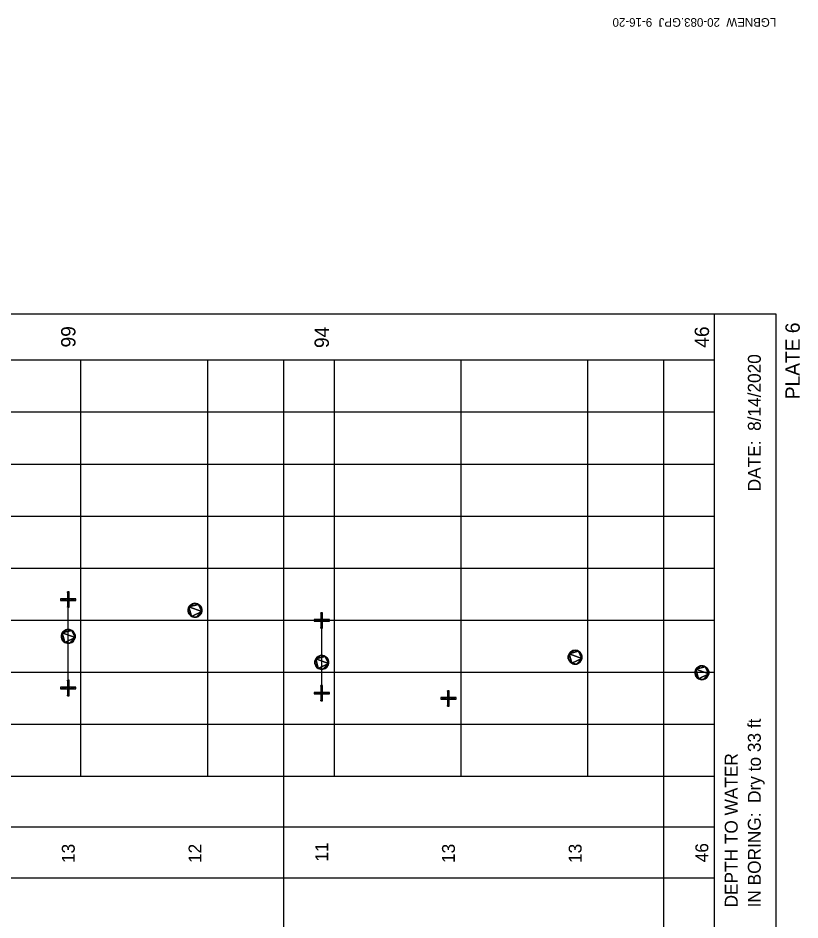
# Model space of a CAD drawing. Extents: x 1313964 to 1316843, y 2087046 to 2096619.
# Drawn here: x 1314106.81 to 1314137.66, y 2089837.67 to 2089873.26 of the extents above; entities that cross this region are included whole.
import ezdxf

# ---------------------------------------------------------------- set-up
doc = ezdxf.new("R2010")
doc.units = 0
doc.layers.add('B-Sub-Contour', color=7, linetype='Continuous')
doc.layers.add('Default', color=7, linetype='Continuous')

# ---------------------------------------------------------------- blocks, each defined once
blk = doc.blocks.new('POINT_DISPLAY')
at = {"layer": 'Default'}
blk.add_line((0, 0), (0, 0), dxfattribs=at)
blk = doc.blocks.new('DMK_101')
at = {"layer": 'Default'}
for points in [[(-14269.212, 2386.584), (-14476.476, 0), (-14269.212, -2386.584), (-14269.212, 2386.584)], [(-12638.532, 6858), (-13653.516, 4690.872), (-14269.212, 2386.584), (-12638.532, 6858)], [(-12638.532, 6858), (-14269.212, 2386.584), (-14269.212, -2386.584), (-12638.532, 6858)], [(-12638.532, 6858), (-14269.212, -2386.584), (-3147.06, -13508.736), (-12638.532, 6858)], [(-3147.06, 13511.784), (-7618.476, 11878.056), (-12638.532, 6858), (-3147.06, 13511.784)], [(6097.524, 11878.056), (-3147.06, 13511.784), (-12638.532, 6858), (6097.524, 11878.056)], [(-7618.476, 11878.056), (-11266.932, 8820.912), (-12638.532, 6858), (-7618.476, 11878.056)], [(-3147.06, -13508.736), (6097.524, 11878.056), (-12638.532, 6858), (-3147.06, -13508.736)], [(-7618.476, 11878.056), (-9578.34, 10506.456), (-11266.932, 8820.912), (-7618.476, 11878.056)], [(-9578.34, 10506.456), (-10456.164, 9698.736), (-11266.932, 8820.912), (-9578.34, 10506.456)], [(-3147.06, 13511.784), (-5451.348, 12893.04), (-7618.476, 11878.056), (-3147.06, 13511.784)], [(1626.108, 13511.784), (-760.476, 13712.952), (-3147.06, 13511.784), (1626.108, 13511.784)], [(6097.524, 11878.056), (1626.108, 13511.784), (-3147.06, 13511.784), (6097.524, 11878.056)], [(-3147.06, -13508.736), (11117.58, -6858), (6097.524, 11878.056), (-3147.06, -13508.736)], [(6097.524, 11878.056), (3930.396, 12893.04), (1626.108, 13511.784), (6097.524, 11878.056)], [(11117.58, 6858), (8060.436, 10506.456), (6097.524, 11878.056), (11117.58, 6858)], [(12751.308, 2386.584), (11117.58, 6858), (6097.524, 11878.056), (12751.308, 2386.584)], [(11117.58, -6858), (12751.308, 2386.584), (6097.524, 11878.056), (11117.58, -6858)], [(9745.98, 8820.912), (8938.26, 9698.736), (8060.436, 10506.456), (9745.98, 8820.912)], [(11117.58, 6858), (9745.98, 8820.912), (8060.436, 10506.456), (11117.58, 6858)], [(12751.308, 2386.584), (12132.564, 4690.872), (11117.58, 6858), (12751.308, 2386.584)], [(11117.58, -6858), (12751.308, -2386.584), (12751.308, 2386.584), (11117.58, -6858)], [(12751.308, -2386.584), (12952.476, 0), (12751.308, 2386.584), (12751.308, -2386.584)], [(-14269.212, -2386.584), (-13653.516, -4690.872), (-12638.532, -6858), (-14269.212, -2386.584)], [(-14269.212, -2386.584), (-12638.532, -6858), (-9578.34, -10506.456), (-14269.212, -2386.584)], [(-14269.212, -2386.584), (-9578.34, -10506.456), (-3147.06, -13508.736), (-14269.212, -2386.584)], [(-12638.532, -6858), (-11266.932, -8817.864), (-9578.34, -10506.456), (-12638.532, -6858)], [(-11266.932, -8817.864), (-10456.164, -9695.688), (-9578.34, -10506.456), (-11266.932, -8817.864)], [(-9578.34, -10506.456), (-7618.476, -11878.056), (-3147.06, -13508.736), (-9578.34, -10506.456)], [(-7618.476, -11878.056), (-5451.348, -12893.04), (-3147.06, -13508.736), (-7618.476, -11878.056)], [(-3147.06, -13508.736), (6097.524, -11878.056), (11117.58, -6858), (-3147.06, -13508.736)], [(-3147.06, -13508.736), (1626.108, -13508.736), (6097.524, -11878.056), (-3147.06, -13508.736)], [(-3147.06, -13508.736), (-760.476, -13716), (1626.108, -13508.736), (-3147.06, -13508.736)], [(1626.108, -13508.736), (3930.396, -12893.04), (6097.524, -11878.056), (1626.108, -13508.736)], [(6097.524, -11878.056), (8060.436, -10506.456), (11117.58, -6858), (6097.524, -11878.056)], [(8060.436, -10506.456), (9745.98, -8817.864), (11117.58, -6858), (8060.436, -10506.456)], [(8060.436, -10506.456), (8938.26, -9695.688), (9745.98, -8817.864), (8060.436, -10506.456)], [(11117.58, -6858), (12132.564, -4690.872), (12751.308, -2386.584), (11117.58, -6858)]]:
    blk.add_lwpolyline(points, close=True, dxfattribs=at)
blk.add_blockref('POINT_DISPLAY', (14479.524, 0), dxfattribs=at)
blk = doc.blocks.new('DMK_99')
at = {"layer": 'Default'}
for points in [[(-1524, -1524), (-1524, 1524), (-15240, 1524), (-1524, -1524)], [(-1524, -1524), (-15240, 1524), (-15240, -1524), (-1524, -1524)], [(1524, 1524), (1524, 15240), (-1524, 15240), (1524, 1524)], [(1524, 1524), (-1524, 15240), (-1524, 1524), (1524, 1524)], [(-1524, -1524), (1524, -1524), (1524, 1524), (-1524, -1524)], [(-1524, -1524), (1524, 1524), (-1524, 1524), (-1524, -1524)], [(1524, -1524), (15240, -1524), (15240, 1524), (1524, -1524)], [(1524, -1524), (15240, 1524), (1524, 1524), (1524, -1524)], [(-1524, -1524), (-1524, -15240), (1524, -15240), (-1524, -1524)], [(-1524, -1524), (1524, -15240), (1524, -1524), (-1524, -1524)]]:
    blk.add_lwpolyline(points, close=True, dxfattribs=at)

msp = doc.modelspace()

# ---------------------------------------------------------------- linework, layer by layer
at = {"layer": 'B-Sub-Contour'}
for points in [[(1314136.725, 2089818.705), (1314136.725, 2089861.576), (1314075.306, 2089861.576), (1314075.306, 2089818.705), (1314136.725, 2089818.705)], [(1314134.292, 2089818.705), (1314134.292, 2089861.576)], [(1314134.292, 2089859.752), (1314082.603, 2089859.752)], [(1314134.292, 2089859.752), (1314089.292, 2089859.752)], [(1314109.292, 2089843.333), (1314109.292, 2089859.752)], [(1314114.292, 2089843.333), (1314114.292, 2089859.752)], [(1314117.292, 2089839.319), (1314117.292, 2089859.752)], [(1314119.292, 2089843.333), (1314119.292, 2089859.752)], [(1314124.292, 2089843.333), (1314124.292, 2089859.752)], [(1314129.292, 2089843.333), (1314129.292, 2089859.752)], [(1314132.292, 2089839.319), (1314132.292, 2089859.752)], [(1314134.292, 2089843.333), (1314134.292, 2089859.752)], [(1314134.292, 2089857.7), (1314089.292, 2089857.7)], [(1314134.292, 2089855.647), (1314089.292, 2089855.647)], [(1314134.292, 2089853.595), (1314089.292, 2089853.595)], [(1314134.292, 2089851.542), (1314089.292, 2089851.542)], [(1314108.792, 2089846.822), (1314108.792, 2089850.311)], [(1314108.792, 2089846.822), (1314108.792, 2089850.311)], [(1314134.292, 2089849.49), (1314089.292, 2089849.49)], [(1314118.792, 2089846.617), (1314118.792, 2089849.49)], [(1314118.792, 2089846.617), (1314118.792, 2089849.49)], [(1314134.292, 2089847.438), (1314089.292, 2089847.438)], [(1314134.292, 2089845.385), (1314089.292, 2089845.385)], [(1314134.292, 2089843.333), (1314082.603, 2089843.333)], [(1314134.292, 2089843.333), (1314089.292, 2089843.333)], [(1314134.292, 2089841.326), (1314082.603, 2089841.326)], [(1314134.292, 2089839.319), (1314082.603, 2089839.319)], [(1314117.292, 2089823.448), (1314117.292, 2089839.319)], [(1314132.292, 2089823.448), (1314132.292, 2089839.319)]]:
    msp.add_lwpolyline(points, dxfattribs=at)

# ---------------------------------------------------------------- block references
at = {"layer": 'B-Sub-Contour', "xscale": 1.9951013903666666e-05, "yscale": 1.9951013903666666e-05, "rotation": 90}
for name, p in [('DMK_99', (1314108.792, 2089850.311)), ('DMK_99', (1314108.792, 2089850.311)), ('DMK_101', (1314113.792, 2089849.901)), ('DMK_101', (1314113.792, 2089849.901)), ('DMK_99', (1314118.792, 2089849.49)), ('DMK_99', (1314118.792, 2089849.49)), ('DMK_101', (1314108.792, 2089848.874)), ('DMK_101', (1314108.792, 2089848.874)), ('DMK_101', (1314118.792, 2089847.848)), ('DMK_101', (1314118.792, 2089847.848)), ('DMK_101', (1314128.792, 2089848.053)), ('DMK_101', (1314128.792, 2089848.053)), ('DMK_101', (1314133.792, 2089847.438)), ('DMK_101', (1314133.792, 2089847.438)), ('DMK_99', (1314108.792, 2089846.822)), ('DMK_99', (1314108.792, 2089846.822)), ('DMK_99', (1314118.792, 2089846.617)), ('DMK_99', (1314118.792, 2089846.617)), ('DMK_99', (1314123.792, 2089846.412)), ('DMK_99', (1314123.792, 2089846.412))]:
    msp.add_blockref(name, p, dxfattribs=at)

# ---------------------------------------------------------------- texts
at = {"layer": 'B-Sub-Contour'}
for s, height, rotation, p in [('LGBNEW  20-083.GPJ  9-16-20', 0.33932, 180, (1314136.725, 2089873.252)), ('PLATE 6', 0.5655, 90, (1314137.655, 2089858.216)), ('99', 0.5655, 90, (1314109.075, 2089860.257)), ('94', 0.5655, 90, (1314119.075, 2089860.236)), ('46', 0.5655, 90, (1314134.075, 2089860.247)), ('DATE:  8/14/2020', 0.50899, 90, (1314136.117, 2089854.583)), ('IN BORING:  Dry to 33 ft', 0.50899, 90, (1314136.117, 2089838.164)), ('DEPTH TO WATER', 0.50899, 90, (1314135.205, 2089838.164)), ('13', 0.509, 90, (1314109.047, 2089839.916)), ('12', 0.509, 90, (1314114.047, 2089839.916)), ('11', 0.509, 90, (1314119.047, 2089839.973)), ('13', 0.509, 90, (1314124.047, 2089839.916)), ('13', 0.509, 90, (1314129.047, 2089839.916)), ('46', 0.509, 90, (1314134.047, 2089839.945))]:
    msp.add_text(s, height=height, rotation=rotation, dxfattribs=at).set_placement(p)

doc.saveas('drawing.dxf')
